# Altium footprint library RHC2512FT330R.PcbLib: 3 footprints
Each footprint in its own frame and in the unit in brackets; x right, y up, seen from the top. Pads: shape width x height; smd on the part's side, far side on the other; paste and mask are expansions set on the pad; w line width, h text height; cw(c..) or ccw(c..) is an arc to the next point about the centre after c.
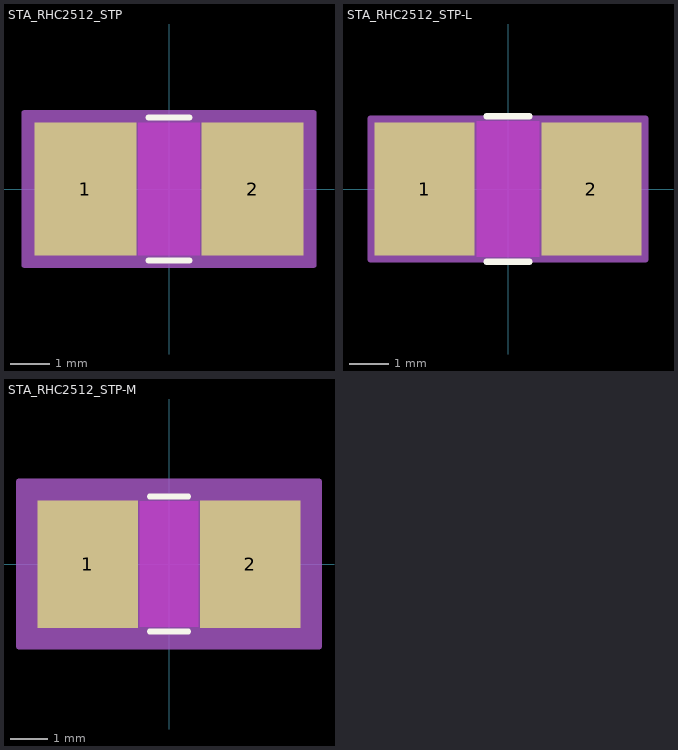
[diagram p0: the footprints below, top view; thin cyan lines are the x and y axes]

## STA_RHC2512_STP [mil]
pads (2):
  rect 103x134 smd paste+0 mask+0: 1(-84.5,0) 2(84.5,0)
Top Layer keep-out:
  region: -31,-65 -31,65 31,65 31,-65
Top Overlay:
  lines w6: -20.89,-72 20.89,-72 ; -20.89,72 20.89,72
Keep-Out Layer:
  region: -31,-67 -31,67 31,67 31,-67
Mechanical 13:
  lines w1: -128,-67 -128,67 ; -128,-67 -33,-67 -33,67 -128,67 ; -128,-67 128,-67 ; -128,-67 -128,67 ; -128,67 128,67 ; 128,-67 33,-67 33,67 128,67 ; 128,-67 128,67 ; 128,-67 128,67
Mechanical 15:
  region: 146,-77 -146,-77 -146,77 146,77
  lines w6: -146,-77 -146,77 146,77 146,-77 -146,-77
3D body "STA_RHC2512_STP.step": height 27.99, standoff 0, extent -127.99,-67.01 127.99,67.01

## STA_RHC2512_STP-L [mil]
pads (2):
  rect 99x132 smd paste+0 mask+0: 1(-82.5,0) 2(82.5,0)
Top Layer keep-out:
  region: -31,-65 -31,65 31,65 31,-65
Top Overlay:
  lines w6: -21.35,-72 21.35,-72 ; -21.35,72 21.35,72
Keep-Out Layer:
  region: -31,-67 -31,67 31,67 31,-67
Mechanical 13:
  lines w1: -128,-67 -128,67 ; -128,-67 -33,-67 -33,67 -128,67 ; -128,-67 128,-67 ; -128,-67 -128,67 ; -128,67 128,67 ; 128,-67 33,-67 33,67 128,67 ; 128,-67 128,67 ; 128,-67 128,67
Mechanical 15:
  region: 136,-70 -136,-70 -136,70 136,70
  lines w6: -136,-70 -136,70 136,70 136,-70 -136,-70
3D body "STA_RHC2512_STP.step": height 27.99, standoff 0, extent -127.99,-67.01 127.99,67.01

## STA_RHC2512_STP-M [mil]
pads (2):
  rect 107x136 smd paste+0 mask+0: 1(-86.5,0) 2(86.5,0)
Top Layer keep-out:
  region: -31,-65 -31,65 31,65 31,-65
Top Overlay:
  lines w6: -20.53,-72 20.53,-72 ; -20.53,72 20.53,72
Keep-Out Layer:
  region: -31,-67 -31,67 31,67 31,-67
Mechanical 13:
  lines w1: -128,-67 -128,67 ; -128,-67 -33,-67 -33,67 -128,67 ; -128,-67 128,-67 ; -128,-67 -128,67 ; -128,67 128,67 ; 128,-67 33,-67 33,67 128,67 ; 128,-67 128,67 ; 128,-67 128,67
Mechanical 15:
  region: 160,-88 -160,-88 -160,88 160,88
  lines w6: -160,-88 -160,88 160,88 160,-88 -160,-88
3D body "STA_RHC2512_STP.step": height 27.99, standoff 0, extent -127.99,-67.01 127.99,67.01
